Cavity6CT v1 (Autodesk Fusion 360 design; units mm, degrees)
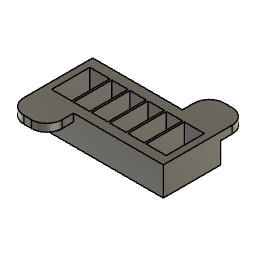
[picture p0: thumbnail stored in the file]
sketch "Sketch1" plane through (0, 0, 0) normal (0, 0, 1) x axis (1, 0, 0)
  line L1 (10.5, 0) -> (0, 0)
  line L2 (10.5, 20) -> (10.5, 0)
  line L3 (0, 20) -> (10.5, 20)
  line L4 (0, 0) -> (0, 20)
  line L5 (20, 0) -> (11.5, 0)
  line L6 (20, 20) -> (20, 0)
  line L7 (11.5, 20) -> (20, 20)
  line L8 (11.5, 0) -> (11.5, 20)
  line L9 (29.5, 0) -> (21, 0)
  line L10 (29.5, 20) -> (29.5, 0)
  line L11 (21, 20) -> (29.5, 20)
  line L12 (21, 0) -> (21, 20)
  line L13 (39, 0) -> (30.5, 0)
  line L14 (39, 20) -> (39, 0)
  line L15 (30.5, 20) -> (39, 20)
  line L16 (30.5, 0) -> (30.5, 20)
  line L17 (48.5, 0) -> (40, 0)
  line L18 (48.5, 20) -> (48.5, 0)
  line L19 (40, 20) -> (48.5, 20)
  line L20 (40, 0) -> (40, 20)
  line L21 (60, 0) -> (49.5, 0)
  line L22 (60, 20) -> (60, 0)
  line L23 (49.5, 20) -> (60, 20)
  line L24 (49.5, 0) -> (49.5, 20)
  line L25 (63.5, -5) -> (-3.5, -5)
  line L26 (63.5, 25) -> (63.5, -5)
  line L27 (-3.5, 25) -> (63.5, 25)
  line L28 (-3.5, -5) -> (-3.5, 25)
  point P1 (0, 0)
  point P2 (0, 0)
  point P3 (10.5, 0)
  point P5 (0, 20)
  point P6 (11.5, 0)
  point P7 (20, 0)
  point P9 (11.5, 20)
  point P10 (21, 0)
  point P11 (29.5, 0)
  point P13 (21, 20)
  point P14 (30.5, 0)
  point P15 (39, 0)
  point P17 (30.5, 20)
  point P18 (40, 0)
  point P19 (48.5, 0)
  point P21 (40, 20)
  point P22 (49.5, 0)
  point P23 (60, 0)
  point P25 (49.5, 20)
  horizontal L1
  vertical L2
  horizontal L3
  vertical L4
  coincident P1 P2
  horizontal L5
  vertical L6
  horizontal L7
  vertical L8
  horizontal L9
  vertical L10
  horizontal L11
  vertical L12
  horizontal L13
  vertical L14
  horizontal L15
  vertical L16
  horizontal L17
  vertical L18
  horizontal L19
  vertical L20
  horizontal L21
  vertical L22
  horizontal L23
  vertical L24
  horizontal L25
  vertical L26
  horizontal L27
  vertical L28
  dimension "d1" distance P2 P3 = 10.5
  dimension "d2" distance P2 P5 = 20
  dimension "d3" distance P6 P7 = 8.5
  dimension "d4" distance P6 P9 = 20
  dimension "d5" distance L2 L8 = 1
  dimension "d6" distance P10 P11 = 8.5
  dimension "d7" distance P10 P13 = 20
  dimension "d8" distance P14 P15 = 8.5
  dimension "d9" distance P14 P17 = 20
  dimension "d10" distance P18 P19 = 8.5
  dimension "d11" distance P18 P21 = 20
  dimension "d12" distance P22 P23 = 10.5
  dimension "d13" distance P22 P25 = 20
  dimension "d14" distance L6 L12 = 1
  dimension "d15" distance L10 L16 = 1
  dimension "d16" distance L14 L20 = 1
  dimension "d17" distance L18 L24 = 1
  dimension "d18" distance L22 L26 = 3.5
  dimension "d19" distance L23 L27 = 5
  dimension "d20" distance L21 L25 = 5
  dimension "d21" distance L4 L28 = 3.5
extrude "Extrude1" new body sketch "Sketch1" against normal blind 15
sketch "Sketch2" plane through (49.5, 0, 0) normal (1, 0, 0) x axis (0, 1, 0)
  line L1 (0, 0) -> (20, 0)
  line L2 (0, -15) -> (0, 0)
  line L3 (20, -15) -> (0, -15)
  line L4 (20, 0) -> (20, -15)
  line L5 (0, -15) -> (20, -15)
  line L6 (0, -12) -> (0, -15)
  line L7 (20, -12) -> (0, -12)
  line L8 (20, -15) -> (20, -12)
  point P5 (20, -15)
  point P6 (20, -15)
  point P9 (20, -12)
  horizontal L5
  vertical L6
  horizontal L7
  vertical L8
  coincident P5 P6
  dimension "d24" distance P6 P9 = 3
extrude "Extrude2" cut sketch "Sketch2" profile of L2 L3 L4 L5 L6 L7 L8 against normal blind 42
sketch "Sketch3" plane through (0, -5, 0) normal (0, -1, 0) x axis (1, 0, 0)
  line L1 (-3.5, 0) -> (63.5, 0)
  line L2 (-3.5, -15) -> (-3.5, 0)
  line L3 (63.5, -15) -> (-3.5, -15)
  line L4 (63.5, 0) -> (63.5, -15)
  line L5 (16.5, 0) -> (-3.5, 0)
  line L6 (16.5, -4) -> (16.5, 0)
  line L7 (-3.5, -4) -> (16.5, -4)
  line L8 (-3.5, 0) -> (-3.5, -4)
  point P3 (-3.5, 0)
  point P6 (-3.5, 0)
  point P7 (16.5, 0)
  point P9 (-3.5, -4)
  horizontal L5
  vertical L6
  horizontal L7
  vertical L8
  coincident P3 P6
  dimension "d27" distance P6 P7 = 20
  dimension "d28" distance P6 P9 = 4
extrude "Extrude3" add sketch "Sketch3" profile of L1 L2 L5 L6 L7 L8 along normal blind 14
fillet "Fillet1" radius 8
sketch "Sketch4" plane through (0, 25, 0) normal (0, 1, 0) x axis (-1, 0, 0)
  line L1 (-63.5, 0) -> (3.5, 0)
  line L2 (-63.5, -15) -> (-63.5, 0)
  line L3 (3.5, -15) -> (-63.5, -15)
  line L4 (3.5, 0) -> (3.5, -15)
  line L5 (-43.5, 0) -> (-63.5, 0)
  line L6 (-43.5, -4) -> (-43.5, 0)
  line L7 (-63.5, -4) -> (-43.5, -4)
  line L8 (-63.5, 0) -> (-63.5, -4)
  point P3 (-63.5, 0)
  point P6 (-63.5, 0)
  point P7 (-43.5, 0)
  point P9 (-63.5, -4)
  horizontal L5
  vertical L6
  horizontal L7
  vertical L8
  coincident P3 P6
  dimension "d33" distance P6 P7 = 20
  dimension "d34" distance P6 P9 = 4
extrude "Extrude4" add sketch "Sketch4" profile of L1 L2 L5 L6 L7 L8 along normal blind 14
fillet "Fillet2" radius 8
